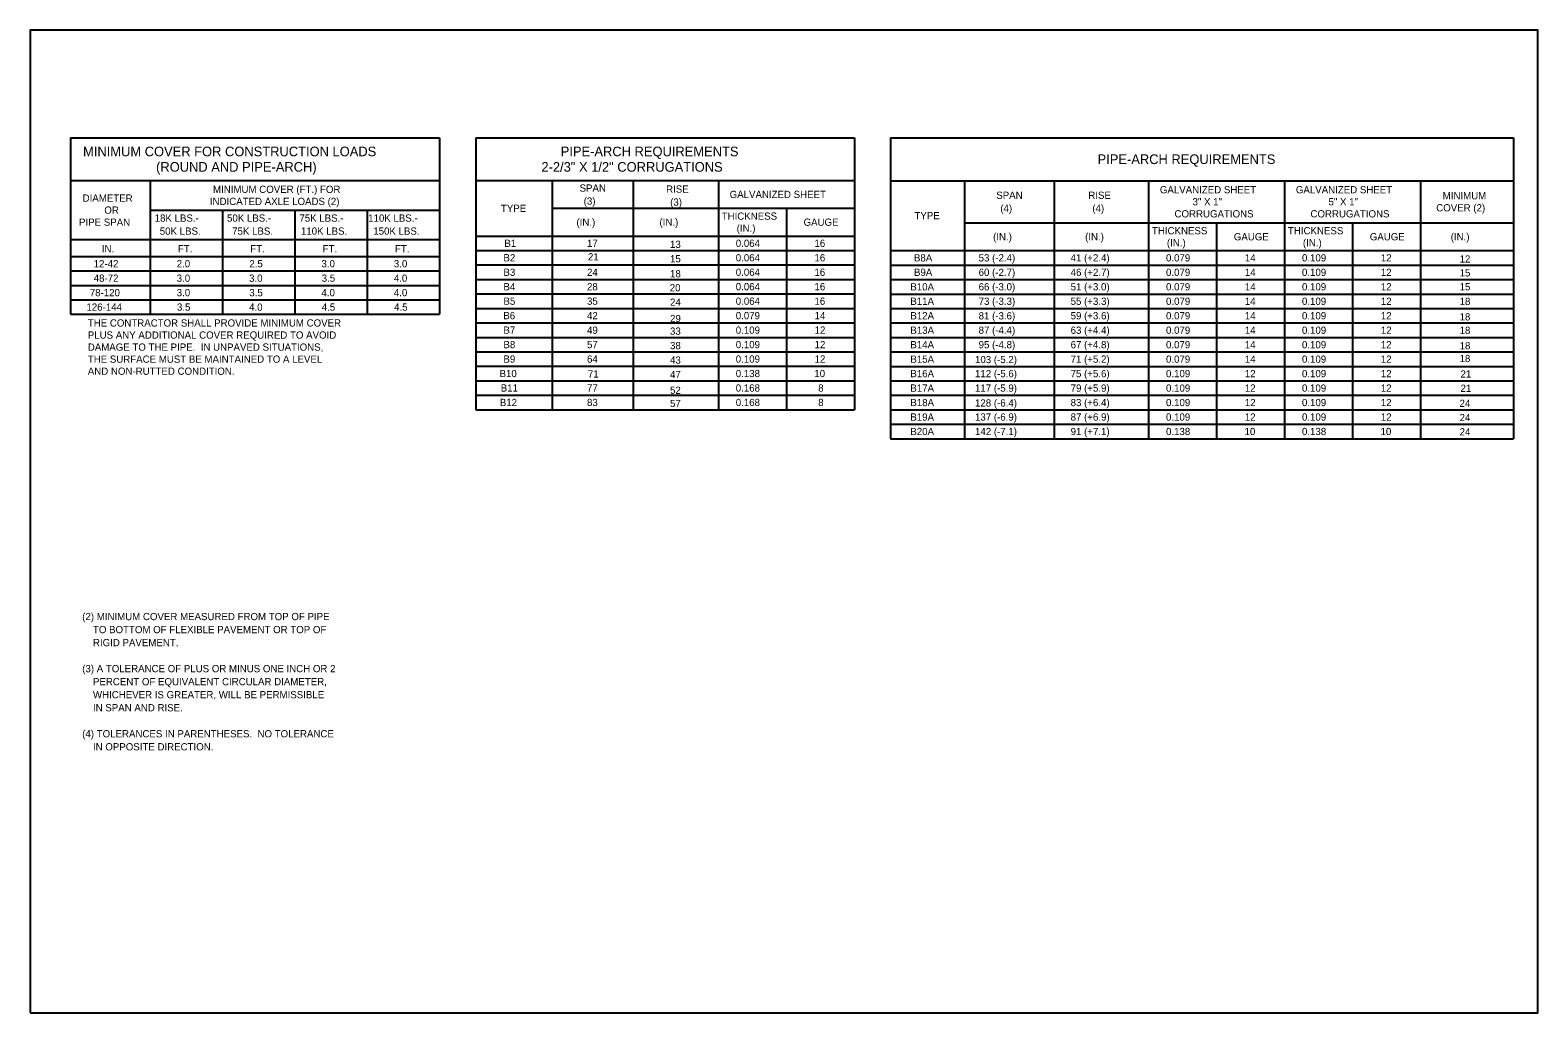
# Model space of a CAD drawing. Extents: x -439.1 to -407.9, y -458.1 to -437.7.
import ezdxf

# ---------------------------------------------------------------- set-up
doc = ezdxf.new("R2010")
doc.units = 0
for name, color, linetype in [('Draft_Named_Boundary', 7, 'Continuous'), ('Level 4', 7, 'Continuous'), ('Level 45', 7, 'Continuous')]:
    doc.layers.add(name, color=color, linetype=linetype)

msp = doc.modelspace()

# ---------------------------------------------------------------- linework, layer by layer
at = {"layer": 'Draft_Named_Boundary'}
msp.add_lwpolyline([(-439.109, -458.051), (-407.859, -458.051), (-407.859, -437.676), (-439.109, -437.676)], close=True, dxfattribs=at)
at = {"layer": 'Level 4'}
for p, q in [((-438.276, -439.907), (-438.276, -443.568)), ((-438.276, -439.907), (-430.622, -439.907)), ((-430.622, -439.907), (-430.622, -443.568)), ((-429.872, -439.907), (-429.872, -445.545)), ((-429.872, -439.907), (-422.026, -439.907)), ((-422.026, -439.907), (-422.026, -445.545)), ((-421.276, -439.907), (-421.276, -446.147)), ((-421.276, -439.907), (-408.365, -439.907)), ((-408.365, -439.907), (-408.365, -446.147)), ((-438.276, -440.795), (-430.622, -440.795)), ((-436.622, -440.795), (-436.622, -443.568)), ((-429.872, -440.795), (-426.149, -440.795)), ((-428.286, -440.795), (-428.286, -445.545)), ((-426.611, -440.795), (-426.611, -445.545)), ((-426.595, -440.795), (-422.026, -440.795)), ((-424.845, -440.795), (-424.845, -445.545)), ((-421.276, -440.797), (-408.365, -440.797)), ((-419.74, -440.797), (-419.74, -446.147)), ((-417.884, -440.797), (-417.884, -446.147)), ((-417.678, -440.797), (-413.247, -440.797)), ((-415.927, -440.797), (-415.927, -446.147)), ((-413.109, -440.797), (-413.109, -446.147)), ((-410.29, -440.797), (-410.29, -446.147)), ((-436.622, -441.407), (-430.622, -441.407)), ((-435.122, -441.407), (-435.122, -443.568)), ((-433.622, -441.407), (-433.622, -443.568)), ((-432.122, -441.407), (-432.122, -443.568)), ((-428.286, -441.37), (-422.026, -441.37)), ((-423.435, -441.37), (-423.435, -445.545)), ((-419.74, -441.672), (-413.109, -441.672)), ((-414.518, -441.672), (-414.518, -446.147)), ((-413.109, -441.672), (-408.365, -441.672)), ((-411.7, -441.672), (-411.7, -446.147)), ((-438.276, -442.019), (-430.622, -442.019)), ((-429.872, -441.945), (-422.026, -441.945)), ((-438.276, -442.368), (-430.622, -442.368)), ((-429.872, -442.245), (-422.026, -442.245)), ((-421.276, -442.247), (-408.365, -442.247)), ((-438.276, -442.668), (-430.622, -442.668)), ((-429.872, -442.545), (-422.026, -442.545)), ((-421.276, -442.547), (-408.365, -442.547)), ((-438.276, -442.968), (-430.622, -442.968)), ((-429.872, -442.845), (-422.026, -442.845)), ((-421.276, -442.847), (-408.365, -442.847)), ((-438.276, -443.268), (-430.622, -443.268)), ((-429.872, -443.145), (-422.026, -443.145)), ((-421.276, -443.147), (-408.365, -443.147)), ((-438.276, -443.568), (-430.622, -443.568)), ((-429.872, -443.445), (-422.026, -443.445)), ((-429.872, -443.745), (-422.026, -443.745)), ((-421.276, -443.447), (-408.365, -443.447)), ((-421.276, -443.747), (-408.365, -443.747)), ((-429.872, -444.045), (-422.026, -444.045)), ((-421.276, -444.047), (-408.365, -444.047)), ((-429.872, -444.345), (-422.026, -444.345)), ((-421.276, -444.347), (-408.365, -444.347)), ((-429.872, -444.645), (-422.026, -444.645)), ((-421.276, -444.647), (-408.365, -444.647)), ((-429.872, -444.945), (-422.026, -444.945)), ((-421.276, -444.947), (-408.365, -444.947)), ((-429.872, -445.245), (-422.026, -445.245)), ((-421.276, -445.247), (-408.365, -445.247)), ((-429.872, -445.545), (-422.026, -445.545)), ((-421.276, -445.547), (-408.365, -445.547)), ((-421.276, -445.847), (-408.365, -445.847)), ((-421.276, -446.147), (-408.365, -446.147))]:
    msp.add_line(p, q, dxfattribs=at)
at = {"layer": 'Level 45'}
for p, q in [((-437.449, -442.518), (-437.449, -442.518)), ((-435.872, -442.518), (-435.872, -442.518)), ((-434.372, -442.518), (-434.372, -442.518)), ((-432.872, -442.518), (-432.872, -442.518)), ((-431.372, -442.518), (-431.372, -442.518)), ((-437.449, -442.818), (-437.449, -442.818)), ((-437.449, -443.118), (-437.449, -443.118)), ((-435.872, -442.818), (-435.872, -442.818)), ((-435.872, -443.118), (-435.872, -443.118)), ((-434.372, -442.818), (-434.372, -442.818)), ((-434.372, -443.118), (-434.372, -443.118)), ((-432.872, -442.818), (-432.872, -442.818)), ((-432.872, -443.118), (-432.872, -443.118)), ((-431.372, -442.818), (-431.372, -442.818)), ((-431.372, -443.118), (-431.372, -443.118)), ((-437.449, -443.418), (-437.449, -443.418)), ((-435.872, -443.418), (-435.872, -443.418)), ((-434.372, -443.418), (-434.372, -443.418)), ((-432.872, -443.418), (-432.872, -443.418)), ((-431.372, -443.418), (-431.372, -443.418))]:
    msp.add_line(p, q, dxfattribs=at)

# ---------------------------------------------------------------- texts
at = {"layer": 'Level 4'}
for s, height, p in [('MINIMUM COVER FOR CONSTRUCTION LOADS', 0.2, (-438.012, -440.291)), ('(ROUND AND PIPE-ARCH)', 0.2, (-436.499, -440.611)), ('SPAN', 0.15, (-427.721, -441.025)), ('RISE', 0.15, (-425.927, -441.046)), ('DIAMETER', 0.15, (-438.021, -441.232)), ('(3)', 0.15, (-427.636, -441.295)), ('(3)', 0.15, (-425.843, -441.316)), ('SPAN', 0.15, (-419.084, -441.174)), ('RISE', 0.15, (-417.177, -441.174)), ('MINIMUM', 0.15, (-409.831, -441.184)), ('OR', 0.15, (-437.571, -441.482)), ('TYPE', 0.15, (-429.351, -441.445)), ('TYPE', 0.15, (-420.78, -441.597)), ('(4)', 0.15, (-419, -441.444)), ('(4)', 0.15, (-417.093, -441.444)), ('COVER (2)', 0.15, (-409.965, -441.434)), ('PIPE SPAN', 0.15, (-438.096, -441.732)), ('B1', 0.15, (-429.28, -442.17)), ('B2', 0.15, (-429.299, -442.47)), ('B8A', 0.15, (-420.79, -442.472)), ('B3', 0.15, (-429.299, -442.77)), ('B9A', 0.15, (-420.79, -442.772)), ('B4', 0.15, (-429.299, -443.07)), ('B10A', 0.15, (-420.865, -443.072)), ('B5', 0.15, (-429.299, -443.37)), ('B11A', 0.15, (-420.865, -443.372)), ('THE CONTRACTOR SHALL PROVIDE MINIMUM COVER ', 0.15, (-437.914, -443.822)), ('B6', 0.15, (-429.302, -443.67)), ('B12A', 0.15, (-420.865, -443.672)), ('PLUS ANY ADDITIONAL COVER REQUIRED TO AVOID ', 0.15, (-437.914, -444.072)), ('B7', 0.15, (-429.299, -443.97)), ('B13A', 0.15, (-420.865, -443.972)), ('DAMAGE TO THE PIPE.  IN UNPAVED SITUATIONS, ', 0.15, (-437.914, -444.322)), ('B8', 0.15, (-429.299, -444.27)), ('B14A', 0.15, (-420.865, -444.272)), ('AND NON-RUTTED CONDITION.', 0.15, (-437.914, -444.822)), ('THE SURFACE MUST BE MAINTAINED TO A LEVEL ', 0.15, (-437.914, -444.572)), ('B9', 0.15, (-429.299, -444.57)), ('B15A', 0.15, (-420.865, -444.572)), ('B10', 0.15, (-429.38, -444.87)), ('B16A', 0.15, (-420.865, -444.872)), ('B11', 0.15, (-429.355, -445.17)), ('B17A', 0.15, (-420.865, -445.172)), ('B12', 0.15, (-429.374, -445.47)), ('B18A', 0.15, (-420.865, -445.472)), ('B19A', 0.15, (-420.865, -445.772)), ('B20A', 0.15, (-420.865, -446.072)), ('(2) MINIMUM COVER MEASURED FROM TOP OF PIPE ', 0.15, (-438.03, -449.909)), ('    TO BOTTOM OF FLEXIBLE PAVEMENT OR TOP OF ', 0.15, (-438.03, -450.179)), ('    RIGID PAVEMENT.', 0.15, (-438.03, -450.449)), ('(3) A TOLERANCE OF PLUS OR MINUS ONE INCH OR 2 ', 0.15, (-438.03, -450.989)), ('    PERCENT OF EQUIVALENT CIRCULAR DIAMETER, ', 0.15, (-438.03, -451.259)), ('    WHICHEVER IS GREATER, WILL BE PERMISSIBLE ', 0.15, (-438.03, -451.529)), ('    IN SPAN AND RISE.', 0.15, (-438.03, -451.799)), ('(4) TOLERANCES IN PARENTHESES.  NO TOLERANCE ', 0.15, (-438.03, -452.339)), ('    IN OPPOSITE DIRECTION.', 0.15, (-438.03, -452.609))]:
    msp.add_text(s, height=height, dxfattribs=at).set_placement(p)
at = {"layer": 'Level 45'}
for s, height, p in [('PIPE-ARCH REQUIREMENTS', 0.2, (-428.112, -440.291)), ('PIPE-ARCH REQUIREMENTS', 0.2, (-416.984, -440.452)), ('2-2/3" X 1/2" CORRUGATIONS', 0.2, (-428.512, -440.611)), ('MINIMUM COVER (FT.) FOR', 0.15, (-435.319, -441.051)), ('GALVANIZED SHEET', 0.15, (-415.693, -441.059)), ('GALVANIZED SHEET', 0.15, (-412.874, -441.059)), ('INDICATED AXLE LOADS (2)', 0.15, (-435.384, -441.301)), ('GALVANIZED SHEET', 0.15, (-424.61, -441.157)), ('3" X 1"', 0.15, (-415.016, -441.309)), ('5" X 1"', 0.15, (-412.198, -441.309)), ('18K LBS.-', 0.15, (-436.528, -441.647)), ('50K LBS.-', 0.15, (-435.028, -441.647)), ('75K LBS.-', 0.15, (-433.528, -441.647)), ('110K LBS.-', 0.15, (-432.103, -441.647)), ('THICKNESS', 0.15, (-424.775, -441.607)), ('CORRUGATIONS', 0.15, (-415.39, -441.559)), ('CORRUGATIONS', 0.15, (-412.572, -441.559)), ('50K LBS.', 0.15, (-436.422, -441.917)), ('75K LBS.', 0.15, (-434.922, -441.917)), ('110K LBS.', 0.15, (-433.497, -441.917)), ('150K LBS.', 0.15, (-431.997, -441.917)), ('(IN.)', 0.15, (-427.786, -441.732)), ('(IN.)', 0.15, (-426.065, -441.732)), ('(IN.)', 0.15, (-424.465, -441.857)), ('GAUGE', 0.15, (-423.078, -441.732)), ('THICKNESS', 0.15, (-415.857, -441.909)), ('THICKNESS', 0.15, (-413.039, -441.909)), ('IN.', 0.15, (-437.623, -442.283)), ('FT.', 0.15, (-436.047, -442.283)), ('FT.', 0.15, (-434.547, -442.283)), ('FT.', 0.15, (-433.047, -442.283)), ('FT.', 0.15, (-431.547, -442.283)), ('17', 0.15, (-427.567, -442.17)), ('13', 0.15, (-425.846, -442.191)), ('0.064', 0.15, (-424.484, -442.17)), ('16', 0.15, (-422.853, -442.17)), ('(IN.)', 0.15, (-419.15, -442.034)), ('(IN.)', 0.15, (-417.243, -442.034)), ('(IN.)', 0.15, (-415.548, -442.159)), ('GAUGE', 0.15, (-414.16, -442.034)), ('(IN.)', 0.15, (-412.729, -442.159)), ('GAUGE', 0.15, (-411.342, -442.034)), ('(IN.)', 0.15, (-409.665, -442.034)), ('12-42', 0.15, (-437.792, -442.593)), ('2.0', 0.15, (-436.071, -442.593)), ('2.5', 0.15, (-434.566, -442.593)), ('3.0', 0.15, (-433.071, -442.593)), ('3.0', 0.15, (-431.571, -442.593)), ('21', 0.15, (-427.548, -442.45)), ('15', 0.15, (-425.847, -442.491)), ('0.064', 0.15, (-424.484, -442.47)), ('16', 0.15, (-422.853, -442.47)), ('53 (-2.4)', 0.15, (-419.45, -442.472)), ('41 (+2.4)', 0.15, (-417.543, -442.472)), ('0.079', 0.15, (-415.566, -442.472)), ('14', 0.15, (-413.932, -442.472)), ('0.109', 0.15, (-412.748, -442.472)), ('12', 0.15, (-411.114, -442.472)), ('12', 0.15, (-409.481, -442.495)), ('48-72', 0.15, (-437.792, -442.893)), ('3.0', 0.15, (-436.071, -442.893)), ('3.0', 0.15, (-434.571, -442.893)), ('3.5', 0.15, (-433.066, -442.893)), ('4.0', 0.15, (-431.571, -442.893)), ('24', 0.15, (-427.567, -442.77)), ('18', 0.15, (-425.846, -442.801)), ('0.064', 0.15, (-424.484, -442.77)), ('16', 0.15, (-422.853, -442.77)), ('60 (-2.7)', 0.15, (-419.45, -442.772)), ('46 (+2.7)', 0.15, (-417.543, -442.772)), ('0.079', 0.15, (-415.566, -442.772)), ('14', 0.15, (-413.932, -442.772)), ('0.109', 0.15, (-412.748, -442.772)), ('12', 0.15, (-411.114, -442.772)), ('15', 0.15, (-409.481, -442.783)), ('78-120', 0.15, (-437.873, -443.193)), ('3.0', 0.15, (-436.071, -443.193)), ('3.5', 0.15, (-434.566, -443.193)), ('4.0', 0.15, (-433.071, -443.193)), ('4.0', 0.15, (-431.571, -443.193)), ('28', 0.15, (-427.567, -443.07)), ('20', 0.15, (-425.852, -443.091)), ('0.064', 0.15, (-424.484, -443.068)), ('0.064', 0.15, (-424.484, -443.07)), ('16', 0.15, (-422.853, -443.068)), ('16', 0.15, (-422.853, -443.07)), ('66 (-3.0)', 0.15, (-419.45, -443.072)), ('51 (+3.0)', 0.15, (-417.543, -443.072)), ('0.079', 0.15, (-415.566, -443.072)), ('14', 0.15, (-413.932, -443.072)), ('0.109', 0.15, (-412.748, -443.072)), ('12', 0.15, (-411.114, -443.072)), ('15', 0.15, (-409.481, -443.071)), ('126-144', 0.15, (-437.942, -443.493)), ('3.5', 0.15, (-436.066, -443.493)), ('4.0', 0.15, (-434.571, -443.493)), ('4.5', 0.15, (-433.066, -443.493)), ('4.5', 0.15, (-431.566, -443.493)), ('35', 0.15, (-427.567, -443.37)), ('24', 0.15, (-425.846, -443.391)), ('0.064', 0.15, (-424.484, -443.37)), ('16', 0.15, (-422.853, -443.37)), ('73 (-3.3)', 0.15, (-419.45, -443.372)), ('55 (+3.3)', 0.15, (-417.543, -443.372)), ('0.079', 0.15, (-415.566, -443.372)), ('14', 0.15, (-413.932, -443.372)), ('0.109', 0.15, (-412.748, -443.372)), ('12', 0.15, (-411.114, -443.372)), ('18', 0.15, (-409.481, -443.375)), ('42', 0.15, (-427.567, -443.67)), ('29', 0.15, (-425.846, -443.73)), ('0.079', 0.15, (-424.484, -443.67)), ('14', 0.15, (-422.85, -443.67)), ('81 (-3.6)', 0.15, (-419.45, -443.674)), ('59 (+3.6)', 0.15, (-417.543, -443.672)), ('0.079', 0.15, (-415.566, -443.672)), ('14', 0.15, (-413.932, -443.672)), ('0.109', 0.15, (-412.748, -443.672)), ('12', 0.15, (-411.114, -443.672)), ('18', 0.15, (-409.481, -443.695)), ('49', 0.15, (-427.567, -443.972)), ('33', 0.15, (-425.846, -443.991)), ('0.109', 0.15, (-424.484, -443.97)), ('12', 0.15, (-422.85, -443.97)), ('87 (-4.4)', 0.15, (-419.45, -443.972)), ('63 (+4.4)', 0.15, (-417.543, -443.972)), ('0.079', 0.15, (-415.566, -443.972)), ('14', 0.15, (-413.932, -443.972)), ('0.109', 0.15, (-412.748, -443.972)), ('12', 0.15, (-411.114, -443.972)), ('18', 0.15, (-409.481, -443.975)), ('57', 0.15, (-427.567, -444.27)), ('38', 0.15, (-425.846, -444.291)), ('0.109', 0.15, (-424.484, -444.27)), ('12', 0.15, (-422.85, -444.27)), ('95 (-4.8)', 0.15, (-419.45, -444.272)), ('67 (+4.8)', 0.15, (-417.543, -444.272)), ('0.079', 0.15, (-415.566, -444.272)), ('14', 0.15, (-413.932, -444.272)), ('0.109', 0.15, (-412.748, -444.272)), ('12', 0.15, (-411.114, -444.272)), ('18', 0.15, (-409.481, -444.295)), ('64', 0.15, (-427.567, -444.57)), ('43', 0.15, (-425.846, -444.591)), ('0.109', 0.15, (-424.484, -444.57)), ('12', 0.15, (-422.85, -444.57)), ('103 (-5.2)', 0.15, (-419.525, -444.58)), ('71 (+5.2)', 0.15, (-417.543, -444.572)), ('0.079', 0.15, (-415.566, -444.572)), ('14', 0.15, (-413.932, -444.572)), ('0.109', 0.15, (-412.748, -444.572)), ('12', 0.15, (-411.114, -444.572)), ('18', 0.15, (-409.481, -444.559)), ('71', 0.15, (-427.548, -444.878)), ('47', 0.15, (-425.846, -444.891)), ('0.138', 0.15, (-424.484, -444.87)), ('10', 0.15, (-422.855, -444.87)), ('112 (-5.6)', 0.15, (-419.525, -444.872)), ('75 (+5.6)', 0.15, (-417.543, -444.872)), ('0.109', 0.15, (-415.566, -444.872)), ('12', 0.15, (-413.932, -444.872)), ('0.109', 0.15, (-412.748, -444.872)), ('12', 0.15, (-411.114, -444.872)), ('21', 0.15, (-409.462, -444.879)), ('77', 0.15, (-427.567, -445.17)), ('52', 0.15, (-425.846, -445.217)), ('0.168', 0.15, (-424.484, -445.17)), ('8', 0.15, (-422.775, -445.17)), ('117 (-5.9)', 0.15, (-419.525, -445.172)), ('79 (+5.9)', 0.15, (-417.543, -445.172)), ('0.109', 0.15, (-415.566, -445.172)), ('12', 0.15, (-413.932, -445.172)), ('0.109', 0.15, (-412.748, -445.172)), ('12', 0.15, (-411.114, -445.172)), ('21', 0.15, (-409.462, -445.175)), ('83', 0.15, (-427.567, -445.47)), ('57', 0.15, (-425.846, -445.491)), ('0.168', 0.15, (-424.484, -445.47)), ('8', 0.15, (-422.775, -445.47)), ('128 (-6.4)', 0.15, (-419.525, -445.48)), ('137 (-6.9)', 0.15, (-419.525, -445.772)), ('83 (+6.4)', 0.15, (-417.543, -445.472)), ('87 (+6.9)', 0.15, (-417.543, -445.772)), ('0.109', 0.15, (-415.566, -445.472)), ('0.109', 0.15, (-415.566, -445.772)), ('12', 0.15, (-413.932, -445.472)), ('12', 0.15, (-413.932, -445.772)), ('0.109', 0.15, (-412.748, -445.472)), ('0.109', 0.15, (-412.748, -445.772)), ('12', 0.15, (-411.114, -445.472)), ('12', 0.15, (-411.114, -445.772)), ('24', 0.15, (-409.481, -445.487)), ('142 (-7.1)', 0.15, (-419.525, -446.072)), ('91 (+7.1)', 0.15, (-417.543, -446.072)), ('0.138', 0.15, (-415.566, -446.072)), ('10', 0.15, (-413.938, -446.072)), ('0.138', 0.15, (-412.748, -446.072)), ('10', 0.15, (-411.119, -446.072)), ('24', 0.15, (-409.481, -445.783)), ('24', 0.15, (-409.481, -446.079))]:
    msp.add_text(s, height=height, dxfattribs=at).set_placement(p)

doc.saveas('drawing.dxf')
